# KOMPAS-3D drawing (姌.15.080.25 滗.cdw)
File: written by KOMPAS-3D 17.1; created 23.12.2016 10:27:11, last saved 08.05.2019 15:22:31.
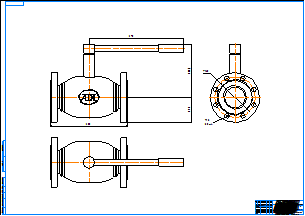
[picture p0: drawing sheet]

Sheet 1: A0, landscape

Title block, sheet 1: name: КШ.15.080.25 фф; material: Внимание! Данный продукт является объектом авторского права ООО «Торговый Дом АДЛ». / Запрещается изменение, копирование, распространение / (в том числе путем копирования на другие сайты и ресурсы в Интернете) / или любое иное использование информации и объектов без предварительного / согласия правообладателя (ООО «Торговый Дом АДЛ»).; sheets: 1; organisation: ООО "Торговый дом АДЛ"; sheet format: A0; stored path: C:\Users\tra\Desktop\2д чертежи\Шаровые краны БИВАЛ\КШ_Бивал_серия_14_15\KOMPAS_2D\КШ.15.080.25 фф.cdw

Views: Вид 1, Проекционный вид 2, Проекционный вид 3
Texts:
  Klimkovich
  ADL
Dimensions and other numbers on the sheet: 300; 370; 205,1; 97,5; 160; 18; 8 Отв.; 1:1; 1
